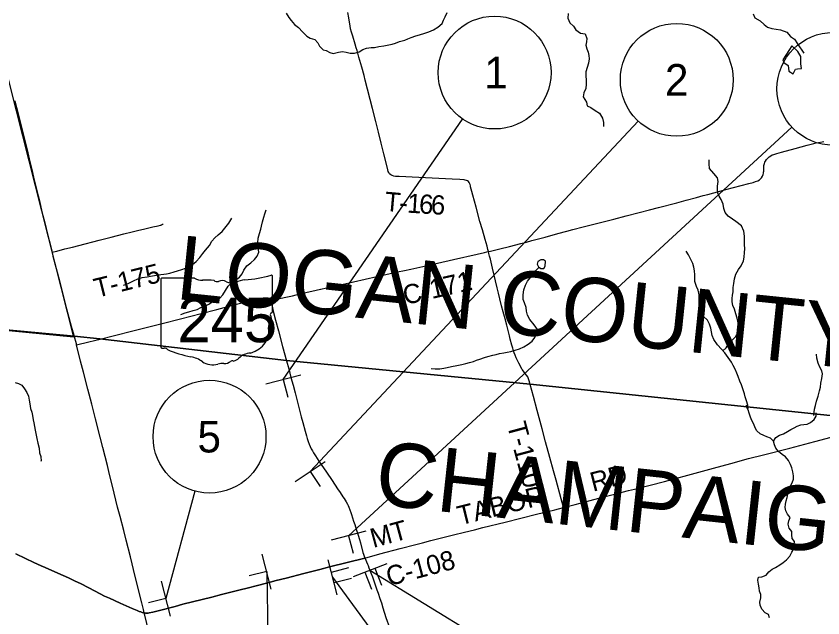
# Model space of a CAD drawing. Extents: x 0 to 1101, y 0 to 440.
# Drawn here: x 300.5 to 372, y 244.3 to 297.7 of the extents above; entities that cross this region are included whole.
import ezdxf

# ---------------------------------------------------------------- set-up
doc = ezdxf.new("R2010")
doc.units = 0
for name, color, linetype in [('Default', 7, 'Continuous'), ('GM_X_County_Road', 7, 'Continuous'), ('GM_X_County_Road_Text', 7, 'Continuous'), ('GM_X_County_Text', 7, 'Continuous'), ('GM_X_Minor_Lake', 7, 'Continuous'), ('GM_X_Minor_River', 7, 'Continuous'), ('GM_X_Section', 7, 'Continuous'), ('GM_X_State_Location', 7, 'Continuous'), ('GM_X_State_Route', 7, 'Continuous'), ('GM_X_State_Shield', 7, 'Continuous'), ('GM_X_Township', 7, 'Continuous'), ('GM_X_Township_Road', 7, 'Continuous'), ('GM_X_Township_Road_Text', 7, 'Continuous'), ('SH_Cut_Line', 7, 'Continuous'), ('SH_Masking', 7, 'Continuous'), ('SH_Text', 7, 'Continuous'), ('SN_P_Signs', 7, 'Continuous')]:
    doc.layers.add(name, color=color, linetype=linetype)

msp = doc.modelspace()

# ---------------------------------------------------------------- linework, layer by layer
at = {"layer": 'Default'}
msp.add_lwpolyline([(331.416, 249.622), (329.836, 249.217), (328.285, 248.832), (327.401, 248.61), (325.995, 248.245), (324.425, 247.846), (323.559, 247.626), (322.818, 247.436), (321.77, 247.171), (321.085, 246.993), (320.237, 246.772), (318.703, 246.378), (317.854, 246.16), (315.285, 245.521), (314.582, 245.339), (313.211, 244.979), (312.612, 244.828), (312.299, 244.766), (312.208, 244.75), (312.133, 244.747), (312.044, 244.747), (311.962, 244.75), (311.852, 244.765), (311.78, 244.779), (311.681, 244.803), (311.541, 244.848), (311.396, 244.899), (311.223, 244.971), (310.777, 245.164), (309.736, 245.622), (308.765, 246.052), (308.345, 246.255), (307.498, 246.688), (306.256, 247.328), (305.671, 247.614), (305.148, 247.858), (304.195, 248.285), (303.069, 248.78), (302.728, 248.93), (302.066, 249.232), (301.324, 249.581), (300.486, 249.988)], dxfattribs=at)
at = {"layer": 'GM_X_County_Road'}
for points in [[(258.549, 348.4), (256.033, 323.55), (255.755, 319.941), (254.279, 304.355), (253.117, 292.401), (251.924, 280.12), (251.38, 274.519), (281.529, 271.532), (305.637, 269.297), (307.931, 269.05), (324.455, 267.133), (346.049, 265.027), (373.771, 262.138), (378.061, 261.761), (380.797, 261.323), (386.092, 260.749), (411.56, 258.243), (435.213, 255.629), (437.137, 278.176), (437.233, 279.3), (439.492, 305.784), (441.919, 334.219), (444.709, 367.542)], [(323.042, 272.521), (323.541, 272.586), (323.883, 272.635), (324.241, 272.706), (324.983, 272.877), (325.771, 273.059), (326.445, 273.207), (327.08, 273.355), (327.461, 273.443), (327.497, 273.452), (328.512, 273.684), (329.365, 273.876), (332.469, 274.57), (333.656, 274.841), (334.312, 274.983), (334.911, 275.114), (335.473, 275.237), (336.807, 275.523), (339.266, 276.082), (341.359, 276.56), (342.012, 276.706), (342.225, 276.753), (342.356, 276.781), (342.524, 276.824), (343.37, 277.019), (344.224, 277.228), (345.231, 277.507), (345.717, 277.636), (346.186, 277.758), (347.373, 278.069), (348.506, 278.376), (349.297, 278.588), (349.837, 278.731), (350.757, 278.971), (352.509, 279.417), (353.465, 279.667), (354.564, 279.954), (355.719, 280.252), (356.64, 280.483), (357.417, 280.683), (359.06, 281.105), (359.887, 281.33), (360.803, 281.58), (361.394, 281.748), (361.789, 281.847), (362.857, 282.129), (363.392, 282.277), (365.442, 282.811), (365.821, 282.912), (366.034, 282.987), (366.219, 283.066), (366.369, 283.156), (366.457, 283.241), (366.548, 283.337), (366.641, 283.482), (366.692, 283.618), (366.728, 283.745), (366.74, 283.83), (366.744, 283.927), (366.75, 284.053), (366.743, 284.149), (366.752, 284.279), (366.761, 284.415), (366.779, 284.512), (366.803, 284.593), (366.849, 284.717), (366.907, 284.812), (366.997, 284.948), (367.106, 285.071), (367.229, 285.179), (367.365, 285.271), (367.51, 285.349), (367.657, 285.396), (367.908, 285.472), (368.315, 285.596), (369.543, 285.925), (370.587, 286.222), (371.184, 286.369), (371.388, 286.415), (371.601, 286.462), (371.93, 286.521), (372.08, 286.54)], [(311.852, 244.765), (311.78, 245.072), (311.644, 245.653), (311.055, 247.985), (310.625, 249.722), (310.253, 251.204), (310.034, 252.071), (309.714, 253.317), (309.498, 254.146), (309.342, 254.76), (309.04, 255.99), (308.788, 257.023), (308.587, 257.837), (308.186, 259.408), (307.953, 260.33), (307.537, 261.954), (307.362, 262.66), (307.205, 263.274), (306.867, 264.592), (306.477, 266.108), (306.222, 267.063), (305.846, 268.511)], [(348.992, 254.096), (350.05, 254.366), (351.365, 254.717), (352.592, 255.034), (353.512, 255.274), (354.755, 255.597), (355.295, 255.734), (357.96, 256.413), (360.999, 257.229), (362.306, 257.594), (363.84, 258.009), (365.403, 258.438), (366.73, 258.783), (369.053, 259.375), (371.278, 259.954), (372.737, 260.332), (374.049, 260.664)], [(331.416, 249.622), (332.746, 249.984), (334.521, 250.46), (335.922, 250.835), (336.499, 250.979), (337.257, 251.171), (338.089, 251.38), (339.264, 251.671), (340.223, 251.907), (341.128, 252.131), (341.869, 252.316), (343.838, 252.816), (346.624, 253.505), (348.234, 253.905), (348.992, 254.096)], [(314.799, 232.868), (314.399, 234.451), (313.899, 236.476), (313.53, 237.998), (312.695, 241.363), (312.273, 243.083), (311.898, 244.564), (311.852, 244.765)]]:
    msp.add_lwpolyline(points, dxfattribs=at)
at = {"layer": 'GM_X_Minor_Lake'}
for points in [[(368.454, 293.786), (368.531, 293.558), (368.902, 293.291), (368.975, 292.789), (369.369, 292.544), (369.568, 292.963), (369.728, 292.983), (370.103, 293.001), (370.041, 293.434), (370.05, 294.071), (369.784, 294.519), (369.245, 295.016)], [(369.245, 295.016), (368.454, 293.786)], [(346.985, 275.293), (347.271, 275.288), (347.377, 275.503), (347.408, 275.926), (347.24, 276.054), (347, 276.047), (346.746, 275.903), (346.684, 275.664), (346.805, 275.433)], [(346.805, 275.433), (346.985, 275.293)]]:
    msp.add_lwpolyline(points, dxfattribs=at)
at = {"layer": 'GM_X_Minor_River'}
for points in [[(324.445, 297.914), (324.656, 297.547), (324.879, 297.259), (325.17, 296.925), (325.519, 296.636), (325.877, 296.267), (326.269, 295.875), (326.563, 295.711), (326.97, 295.592), (327.239, 295.304), (327.394, 295.006), (327.696, 294.683), (327.991, 294.622), (328.307, 294.436), (328.601, 294.352), (329.057, 294.471), (329.434, 294.535), (329.762, 294.473), (330.091, 294.378), (330.489, 294.384), (330.888, 294.504), (331.232, 294.704), (331.564, 294.825), (331.962, 294.876), (332.246, 294.884), (332.657, 294.958), (333.089, 295.009), (333.523, 295.106), (333.83, 295.159), (334.116, 295.269), (334.471, 295.412), (334.939, 295.531), (335.224, 295.652), (335.522, 295.762), (335.91, 295.905), (336.252, 296.003), (336.72, 296.133), (337.063, 296.254), (337.498, 296.442), (337.876, 296.664), (338.256, 297.001), (338.374, 297.295), (338.515, 297.589), (338.702, 297.985)], [(349.409, 297.89), (349.381, 297.48), (349.568, 297.057), (349.894, 296.779), (350.105, 296.447), (350.521, 296.156), (350.918, 296.094), (351.072, 295.671), (351.033, 295.376), (350.984, 295.08), (351.07, 294.772), (351.202, 294.463), (351.244, 294.167), (351.273, 293.859), (351.234, 293.484), (351.092, 293.099), (350.973, 292.713), (350.99, 292.315), (351.009, 292.03), (351.003, 291.632), (350.986, 291.234), (350.821, 290.849), (350.759, 290.497), (351.048, 290.038), (351.112, 289.718), (351.439, 289.543), (351.799, 289.277), (352.205, 289.044), (352.472, 288.619), (352.546, 288.242), (352.552, 287.867)], [(365.803, 297.861), (365.968, 297.517), (366.419, 297.249), (366.79, 296.926), (367.082, 296.671), (367.467, 296.552), (367.853, 296.501), (368.227, 296.439), (368.781, 296.227), (369.128, 295.857), (369.477, 295.602), (369.744, 295.189), (370.294, 294.372)], [(363.131, 267.984), (363.412, 268.257), (363.589, 268.551), (363.88, 268.889), (364.264, 269.248), (364.522, 269.643), (364.531, 270.112), (364.493, 270.478), (364.398, 270.892), (364.268, 271.283), (364.15, 271.674), (363.997, 272.019), (363.946, 272.34), (363.963, 272.626), (363.992, 272.934), (364.031, 273.219), (364.05, 273.596), (364.092, 273.972), (364.168, 274.383), (364.267, 274.792), (364.514, 275.188), (364.761, 275.538), (364.963, 275.98), (365.015, 276.288), (365.045, 276.699), (365.063, 277.042), (365.059, 277.419), (365.032, 277.797), (365.039, 278.14), (364.99, 278.586), (364.771, 279.059), (364.287, 279.456), (363.995, 279.668), (363.612, 279.937), (363.332, 280.24), (363.225, 280.607), (363.152, 280.986), (362.989, 281.4), (362.789, 281.69), (362.692, 281.977), (362.641, 282.298), (362.658, 282.584), (362.712, 283.006), (362.661, 283.338), (362.326, 283.722), (361.957, 284.151), (361.908, 284.564), (361.915, 284.929)], [(315.088, 271.213), (315.49, 271.354), (315.812, 271.44), (316.202, 271.559), (316.558, 271.667), (316.857, 271.821), (317.145, 271.919), (317.571, 272.14), (317.86, 272.295), (318.205, 272.449), (318.528, 272.637), (318.808, 272.941), (319.043, 273.325), (319.291, 273.721), (319.605, 274.07), (319.917, 274.224), (320.299, 274.526), (320.544, 274.819), (320.687, 275.148), (320.946, 275.509), (321.305, 275.8), (321.63, 276.091), (321.875, 276.395), (322.008, 276.747), (321.958, 277.137), (321.921, 277.572), (321.963, 277.983), (322.073, 278.381), (322.183, 278.768), (322.257, 279.052), (322.344, 279.428), (322.466, 279.837), (322.541, 280.145), (322.65, 280.474)], [(310.013, 273.808), (310.438, 273.949), (310.899, 274.192), (311.279, 274.38), (311.669, 274.487), (312.116, 274.559), (312.402, 274.599), (312.78, 274.661), (313.101, 274.724), (313.833, 274.825), (314.12, 274.888), (314.521, 274.984), (314.808, 275.07), (315.198, 275.189), (315.509, 275.321), (315.797, 275.441), (316.12, 275.63), (316.468, 275.909), (316.783, 276.27), (317.052, 276.608), (317.274, 276.901), (317.625, 277.34), (317.849, 277.714), (318.106, 278.006), (318.396, 278.264), (318.767, 278.566), (319.129, 279.005), (319.352, 279.299), (319.611, 279.74)], [(365.364, 262.885), (365.335, 263.169), (365.217, 263.56), (365.098, 263.905), (365.046, 264.192), (364.906, 264.629), (364.776, 264.963), (364.645, 265.308), (364.482, 265.723), (364.362, 266.022), (364.22, 266.379), (364.055, 266.702), (363.89, 266.991), (363.589, 267.397), (363.3, 267.802), (362.998, 268.127), (362.641, 268.534), (362.33, 269.008), (362.188, 269.342), (362.115, 269.675), (362.052, 269.985), (361.945, 270.364), (361.758, 270.711), (361.376, 271.049), (361.2, 271.372), (361.048, 271.809), (361.022, 272.244), (361.018, 272.599), (361.013, 272.965), (360.929, 273.355), (360.799, 273.689), (360.648, 274.137), (360.642, 274.423), (360.648, 274.732), (360.62, 275.087), (360.558, 275.419), (360.461, 275.718), (360.285, 276.076), (360.076, 276.502), (359.877, 276.826)], [(337.275, 266.419), (337.64, 266.39), (338.062, 266.383), (338.406, 266.457), (338.703, 266.509), (339.082, 266.605), (339.551, 266.7), (339.998, 266.772), (340.342, 266.858), (340.663, 266.943), (341.019, 267.052), (341.306, 267.149), (341.594, 267.259), (341.995, 267.389), (342.305, 267.486), (342.742, 267.616), (343.04, 267.679), (343.349, 267.743), (343.727, 267.816), (344.025, 267.88), (344.346, 267.943), (344.735, 268.039), (345.115, 268.181), (345.495, 268.357), (345.875, 268.567), (346.235, 268.858), (346.457, 269.163), (346.624, 269.526), (346.688, 269.891), (346.399, 270.307), (346.009, 270.772), (345.822, 271.163), (345.738, 271.508), (345.698, 271.84), (345.558, 272.243), (345.438, 272.542), (345.423, 272.954), (345.488, 273.387), (345.644, 273.796), (345.822, 274.158), (346.08, 274.485), (346.302, 274.79), (346.513, 275.084), (346.851, 275.397)], [(371.199, 262.267), (371.241, 262.811), (371.327, 263.141), (371.426, 263.539), (371.559, 263.96), (371.694, 264.437), (371.769, 264.779), (371.798, 265.11), (371.897, 265.531), (371.951, 265.942), (371.888, 266.229), (371.734, 266.54), (371.558, 266.898), (371.452, 267.334), (371.414, 267.701)], [(300.405, 265.177), (300.713, 265.094), (301.02, 264.942), (301.245, 264.631), (301.46, 264.298), (301.605, 263.965), (301.671, 263.621), (301.725, 263.277), (301.79, 262.888), (301.889, 262.544), (301.944, 262.257), (302.009, 261.879), (302.087, 261.593), (302.141, 261.284), (302.184, 260.963), (302.261, 260.665), (302.337, 260.23), (302.413, 259.806), (302.558, 259.358), (302.589, 258.946), (302.689, 258.637), (302.731, 258.224), (302.719, 258.247)], [(366.141, 260.888), (365.984, 261.176), (365.872, 261.485), (365.704, 261.807), (365.569, 262.117), (365.47, 262.461), (365.358, 262.748), (365.223, 263.035), (365.225, 263.161)], [(367.605, 259.985), (367.826, 260.301), (368.159, 260.515), (368.492, 260.638), (368.847, 260.83), (369.146, 261.01), (369.433, 261.179), (369.72, 261.302), (370.029, 261.425), (370.315, 261.468), (370.601, 261.5), (370.888, 261.623), (371.21, 261.906), (371.384, 262.19), (371.387, 262.499)], [(367.25, 244.318), (367.161, 244.616), (366.866, 244.756), (366.594, 245.078), (366.438, 245.434), (366.395, 245.721), (366.478, 246.097), (366.48, 246.383), (366.369, 246.681), (366.337, 246.979), (366.283, 247.311), (366.218, 247.655), (366.289, 247.94), (366.586, 247.96), (366.964, 248.094), (367.195, 248.412), (367.494, 248.627), (367.781, 248.784), (368.171, 249.01), (368.459, 249.224), (368.758, 249.473), (369.058, 249.802), (369.244, 250.155), (369.452, 250.496), (369.444, 250.782), (369.48, 251.079), (369.266, 251.367), (369.246, 251.687), (369.226, 251.974), (369.011, 252.284), (368.923, 252.617), (368.971, 252.914), (369.077, 253.21), (368.851, 253.521), (368.705, 253.808), (368.651, 254.106), (368.688, 254.403), (368.736, 254.689), (368.818, 254.985), (368.878, 255.282), (368.973, 255.624), (369.101, 255.966), (369.275, 256.285), (369.381, 256.616), (369.372, 256.902), (369.318, 257.268), (369.253, 257.612), (369.119, 257.922), (368.95, 258.278), (368.679, 258.589), (368.384, 258.809), (368.066, 259.052), (367.829, 259.375), (367.706, 259.662), (367.618, 259.971), (367.358, 260.26), (367.027, 260.377), (366.743, 260.494), (366.436, 260.634), (366.141, 260.888)]]:
    msp.add_lwpolyline(points, dxfattribs=at)
at = {"layer": 'GM_X_Section'}
msp.add_lwpolyline([(284.164, 302.086), (297.548, 301.138), (299.942, 291.467), (305.596, 269.192), (281.404, 271.573)], close=True, dxfattribs=at)
at = {"layer": 'GM_X_State_Route'}
msp.add_line((305.644, 269.281), (305.683, 269.133), dxfattribs=at)
for points in [[(300.389, 290.148), (300.533, 289.55), (300.882, 288.178), (301.128, 287.22), (301.47, 285.807), (301.668, 285.012), (301.9, 284.052), (302.057, 283.381), (302.321, 282.275), (302.563, 281.279), (302.796, 280.319), (303.038, 279.322), (303.309, 278.218), (303.537, 277.315), (303.687, 276.722), (303.77, 276.393), (304.333, 274.191), (304.636, 272.999), (304.978, 271.701), (305.395, 270.181), (305.644, 269.281)], [(307.937, 269.034), (309.111, 269.318), (310.958, 269.79), (313.457, 270.425), (315.065, 270.833), (316.906, 271.302), (318.293, 271.667), (319.914, 272.088), (320.998, 272.359), (321.739, 272.54), (322.101, 272.625), (322.227, 272.649), (322.322, 272.669), (322.435, 272.688), (322.588, 272.698), (322.7, 272.692), (322.796, 272.675), (322.874, 272.65), (322.957, 272.604), (323.004, 272.567), (323.042, 272.521), (323.071, 272.452), (323.092, 272.368), (323.291, 271.52), (323.495, 270.7), (323.748, 269.749), (324.118, 268.382), (324.461, 267.117)], [(305.683, 269.133), (305.761, 268.837), (305.846, 268.511), (306.936, 268.782), (307.937, 269.034)], [(324.461, 267.117), (324.654, 266.408), (324.855, 265.632), (325.04, 264.949), (325.221, 264.265), (325.492, 263.206), (325.769, 262.143), (325.903, 261.642), (326.11, 260.881), (326.233, 260.451), (326.303, 260.218), (326.39, 259.941), (326.469, 259.724), (326.558, 259.512), (326.661, 259.295), (326.755, 259.117), (326.849, 258.959), (327.026, 258.678), (327.337, 258.219), (327.994, 257.242), (328.504, 256.484), (328.992, 255.757), (329.21, 255.432), (329.456, 255.059), (329.571, 254.889), (329.749, 254.609), (329.867, 254.402), (329.931, 254.274), (329.987, 254.147), (330.082, 253.906), (330.166, 253.66), (330.225, 253.484), (330.412, 252.898), (330.508, 252.597), (330.642, 252.171), (330.802, 251.655), (330.919, 251.263), (331.005, 250.958), (331.233, 250.126), (331.281, 249.965), (331.34, 249.798), (331.416, 249.622)], [(300.486, 249.988), (301.324, 249.581), (302.066, 249.232), (302.728, 248.93), (303.069, 248.78), (304.195, 248.285), (305.148, 247.858), (305.671, 247.614), (306.256, 247.328), (307.498, 246.688), (308.345, 246.255), (308.765, 246.052), (309.736, 245.622), (310.777, 245.164), (311.223, 244.971), (311.396, 244.899), (311.541, 244.848), (311.681, 244.803), (311.78, 244.779), (311.852, 244.765), (311.962, 244.75), (312.044, 244.747), (312.133, 244.747), (312.208, 244.75), (312.299, 244.766), (312.612, 244.828), (313.211, 244.979), (314.582, 245.339), (315.285, 245.521), (317.854, 246.16), (318.703, 246.378), (320.237, 246.772), (321.085, 246.993), (321.77, 247.171), (322.818, 247.436), (323.559, 247.626), (324.425, 247.846), (325.995, 248.245), (327.401, 248.61), (328.285, 248.832), (329.836, 249.217), (331.416, 249.622)], [(331.416, 249.622), (331.436, 249.57), (331.549, 249.294), (331.635, 249.087), (331.691, 248.949), (331.766, 248.759), (331.935, 248.325), (332.072, 247.959), (332.17, 247.679), (332.473, 246.82), (332.575, 246.52), (332.738, 246.044), (332.869, 245.656), (333.01, 245.213), (333.274, 244.361), (333.575, 243.479)]]:
    msp.add_lwpolyline(points, dxfattribs=at)
at = {"layer": 'GM_X_State_Shield'}
for p, q in [((323.217, 271.445), (323.217, 274.586)), ((313.329, 274.334), (313.329, 268.33)), ((316.322, 274.437), (313.427, 274.437)), ((323.216, 271.446), (323.217, 271.445))]:
    msp.add_line(p, q, dxfattribs=at)
for centre, major_axis, start_param, end_param in [((319.695, 282.622), (10.486, 0), 4.814394, 5.042369), ((323.107, 274.599), (0.11, 0), 6.141152, 7.989035), ((313.443, 274.346), (0.115, 0), 1.712693, 3.28349), ((317.012, 275.134), (1.111, 0), 4.042523, 4.731795), ((317.38, 271.066), (3.989, 0), 1.404758, 1.657858), ((318.286, 274.378), (0.321, 0), 3.836095, 5.185415), ((318.756, 273.684), (0.666, 0), 0.950623, 2.079405), ((319.616, 274.635), (0.802, 0), 4.081561, 5.145723), ((321.032, 272.603), (2.11, 0), 1.699011, 2.107814), ((323.191, 271.215), (0.17, 0), 1.883978, 3.671073), ((322.108, 270.818), (1.023, 0), 5.934695, 6.695948), ((323.099, 271.433), (0.118, 0), 5.05454, 6.418171), ((323.611, 270.131), (0.744, 0), 2.387724, 3.262537), ((320.282, 269.731), (2.623, 0), 5.101752, 6.440018), ((313.444, 268.317), (0.116, 0), 3.00124, 4.508301), ((313.461, 268.931), (0.882, 0), 4.665946, 4.897461), ((313.642, 267.984), (0.318, 0), 0.519207, 1.627899), ((317.656, 273.378), (7.572, 0), 4.195997, 4.488961), ((315.399, 265.633), (2.369, 0), 0.823519, 1.323587), ((321.388, 266.645), (1.436, 0), 1.647645, 2.488434), ((317.961, 267.954), (1.503, 0), 4.026481, 4.996735), ((318.83, 265.878), (1.235, 0), 1.495662, 1.94098), ((318.94, 267.504), (0.801, 0), 4.691044, 5.507374), ((319.664, 266.923), (0.226, 0), 1.147584, 2.315152), ((319.568, 267.748), (0.847, 0), 4.937069, 5.64225)]:
    msp.add_ellipse(centre, major_axis=major_axis, ratio=0.8, start_param=start_param, end_param=end_param, dxfattribs=at)
at = {"layer": 'GM_X_Township'}
msp.add_lwpolyline([(189.224, 280.089), (205.419, 278.858), (219.953, 277.58), (235.998, 275.889), (239.628, 275.54), (251.141, 274.543), (251.38, 274.519), (281.529, 271.532), (305.637, 269.297), (307.931, 269.05), (324.455, 267.133), (346.049, 265.027), (373.771, 262.138), (378.061, 261.761), (380.797, 261.323), (380.697, 259.316), (380.197, 255.256), (378.028, 238.099), (373.82, 204.757), (373.469, 201.961), (371.877, 189.376), (367.226, 152.429)], dxfattribs=at)
at = {"layer": 'GM_X_Township_Road'}
for points in [[(330.711, 294.623), (330.645, 294.856), (330.554, 295.16), (330.326, 295.882), (330.223, 296.242), (330.142, 296.54), (330.093, 296.796), (330.037, 297.125), (329.975, 297.51), (329.902, 297.989)], [(342.356, 276.781), (342.311, 276.963), (342.231, 277.255), (342.058, 277.864), (341.819, 278.704), (341.599, 279.462), (341.258, 280.716), (340.967, 281.773), (340.877, 282.102), (340.778, 282.523), (340.76, 282.609), (340.722, 282.743), (340.686, 282.843), (340.641, 282.921), (340.579, 282.997), (340.496, 283.055), (340.413, 283.096), (340.306, 283.127), (340.198, 283.142), (339.815, 283.17), (339.13, 283.204), (336.202, 283.342), (334.44, 283.434), (334.13, 283.449), (333.96, 283.476), (333.814, 283.523), (333.703, 283.588), (333.602, 283.675), (333.526, 283.783), (333.481, 283.885), (333.436, 284.022), (333.368, 284.302), (333.094, 285.463), (332.864, 286.405), (332.619, 287.363), (332.379, 288.32), (332.085, 289.473), (331.446, 291.988), (331.345, 292.399), (331.145, 293.119), (330.882, 294.01), (330.711, 294.623)], [(303.687, 276.722), (303.802, 276.751), (304.111, 276.831), (304.833, 277.017), (305.501, 277.188), (306.047, 277.328), (307.85, 277.792), (308.933, 278.073), (310.054, 278.357), (310.777, 278.533), (311.265, 278.657), (311.913, 278.816), (312.608, 278.972), (313.083, 279.075), (313.288, 279.123), (313.341, 279.135), (313.384, 279.15), (313.421, 279.166), (313.458, 279.184), (313.497, 279.21), (313.529, 279.232)], [(346.056, 265.011), (345.962, 265.334), (345.907, 265.502), (345.867, 265.608), (345.833, 265.671), (345.741, 265.822), (345.617, 265.983), (345.449, 266.196), (345.357, 266.33), (345.307, 266.404), (345.056, 266.892), (344.913, 267.183), (344.826, 267.364), (344.716, 267.62), (344.637, 267.823), (344.581, 267.973), (344.536, 268.12), (344.503, 268.236), (344.429, 268.496), (344.289, 269.035), (344.22, 269.324), (344.078, 269.897), (343.986, 270.256), (343.839, 270.829), (343.672, 271.437), (343.523, 271.973), (343.352, 272.604), (343.239, 273.09), (343.123, 273.581), (342.726, 275.325), (342.533, 276.103), (342.46, 276.393), (342.402, 276.622), (342.356, 276.781)], [(348.992, 254.096), (348.793, 254.861), (348.346, 256.517), (348.12, 257.344), (347.803, 258.532), (347.424, 259.916), (347.11, 261.086), (346.674, 262.706), (346.345, 263.93), (346.056, 265.011)]]:
    msp.add_lwpolyline(points, dxfattribs=at)
at = {"layer": 'SH_Cut_Line'}
for points in [[(445.064, 254.562), (435.213, 255.629), (411.56, 258.243), (386.092, 260.749), (380.797, 261.323), (378.061, 261.761), (373.771, 262.138), (346.049, 265.027), (324.455, 267.133), (307.931, 269.05), (305.637, 269.297), (281.529, 271.532), (251.38, 274.519), (251.141, 274.543), (239.628, 275.54), (235.998, 275.889), (219.953, 277.58), (205.419, 278.858), (189.224, 280.089)], [(189.224, 280.089), (205.419, 278.858), (219.953, 277.58), (235.998, 275.889), (239.628, 275.54), (251.141, 274.543), (251.38, 274.519), (281.529, 271.532), (305.637, 269.297), (307.931, 269.05), (324.455, 267.133), (346.049, 265.027), (373.771, 262.138), (378.061, 261.761), (380.797, 261.323), (386.092, 260.749), (411.56, 258.243), (435.213, 255.629), (445.064, 254.562)]]:
    msp.add_lwpolyline(points, dxfattribs=at)
at = {"layer": 'SH_Masking'}
for centre in [(342.901, 292.653), (359.043, 292.01), (372.92, 291.212), (317.642, 260.382)]:
    msp.add_circle(centre, 5, dxfattribs=at)
at = {"layer": 'SH_Text'}
for p, q in [((324.176, 265.435), (340.067, 288.533)), ((326.551, 257.3), (355.626, 288.36)), ((329.955, 251.598), (369.245, 287.822)), ((316.343, 255.553), (313.782, 246.032)), ((322.712, 248.43), (323.008, 231.513)), ((331.851, 248.542), (344.664, 240.695)), ((333.25, 241.569), (328.556, 247.921))]:
    msp.add_line(p, q, dxfattribs=at)
for centre in [(342.901, 292.653), (359.043, 292.01), (372.92, 291.212), (317.642, 260.382)]:
    msp.add_circle(centre, 5, dxfattribs=at)
at = {"layer": 'SN_P_Signs'}
for p, q in [((325.725, 265.837), (322.627, 265.033)), ((324.176, 265.435), (324.578, 263.886)), ((325.224, 256.407), (327.879, 258.193)), ((326.551, 257.3), (327.444, 255.972)), ((331.504, 252), (328.407, 251.196)), ((329.955, 251.598), (330.357, 250.049)), ((323.104, 246.878), (322.32, 249.981)), ((328.953, 246.372), (328.159, 249.471)), ((328.437, 248.386), (329.987, 248.784)), ((333.342, 249.121), (330.359, 247.963)), ((322.712, 248.43), (321.161, 248.037)), ((331.403, 248.368), (331.982, 246.876)), ((331.851, 248.542), (331.851, 248.542)), ((331.851, 248.542), (331.851, 248.542)), ((332.298, 248.715), (332.877, 247.224)), ((314.174, 244.48), (313.39, 247.583)), ((328.556, 247.921), (328.556, 247.921)), ((328.556, 247.921), (328.556, 247.921)), ((328.675, 247.457), (330.225, 247.854)), ((313.782, 246.032), (312.231, 245.639))]:
    msp.add_line(p, q, dxfattribs=at)

# ---------------------------------------------------------------- texts
at = {"layer": 'GM_X_County_Road_Text'}
for s, rotation, p in [('C-171', 12.82896, (334.989, 272.048)), ('RD', 14.51963, (351.617, 255.495)), ('TABOR', 13.98887, (339.84, 252.52)), ('MT', 15.25359, (332.142, 250.514)), ('C-108', 14.82754, (333.548, 247.129))]:
    msp.add_text(s, height=1.7045, rotation=rotation, dxfattribs=at).set_placement(p)
at = {"layer": 'GM_X_County_Text'}
for s, rotation, p in [('LOGAN COUNTY', 354.10872, (314.55, 272.594)), ('CHAMPAIGN COUNTY', 353.83976, (332.148, 254.403))]:
    msp.add_text(s, height=5.68182, rotation=rotation, dxfattribs=at).set_placement(p)
at = {"layer": 'GM_X_State_Location'}
for s in ['s', 'r']:
    msp.add_text(s, height=0.00568, dxfattribs=at).set_placement((318.162, 270.933))
msp.add_text('245', height=0.00568, rotation=0.00001, dxfattribs=at).set_placement((316.156, 270.519))
at = {"layer": 'GM_X_State_Shield'}
msp.add_text('245', height=3.9551, dxfattribs=at).set_placement((314.803, 268.753))
at = {"layer": 'GM_X_Township_Road_Text'}
for s, height, rotation, p in [('T', 1.705, 354.94914, (333.1, 280.403)), ('1', 1.705, 356.46861, (335.118, 280.242)), ('6', 1.705, 356.53591, (336.168, 280.177)), ('6', 1.705, 356.54798, (337.216, 280.113)), ('-', 1.705, 356.29591, (334.414, 280.287)), ('T-175', 1.7045, 13.94728, (307.641, 272.678)), ('T-110', 1.7045, 284.99022, (343.981, 261.444))]:
    msp.add_text(s, height=height, rotation=rotation, dxfattribs=at).set_placement(p)
at = {"layer": 'SH_Text'}
for s, p in [('1', (341.984, 291.253)), ('2', (357.998, 290.61)), ('5', (316.572, 258.982))]:
    msp.add_text(s, height=2.8, rotation=360, dxfattribs=at).set_placement(p)

doc.saveas('drawing.dxf')
